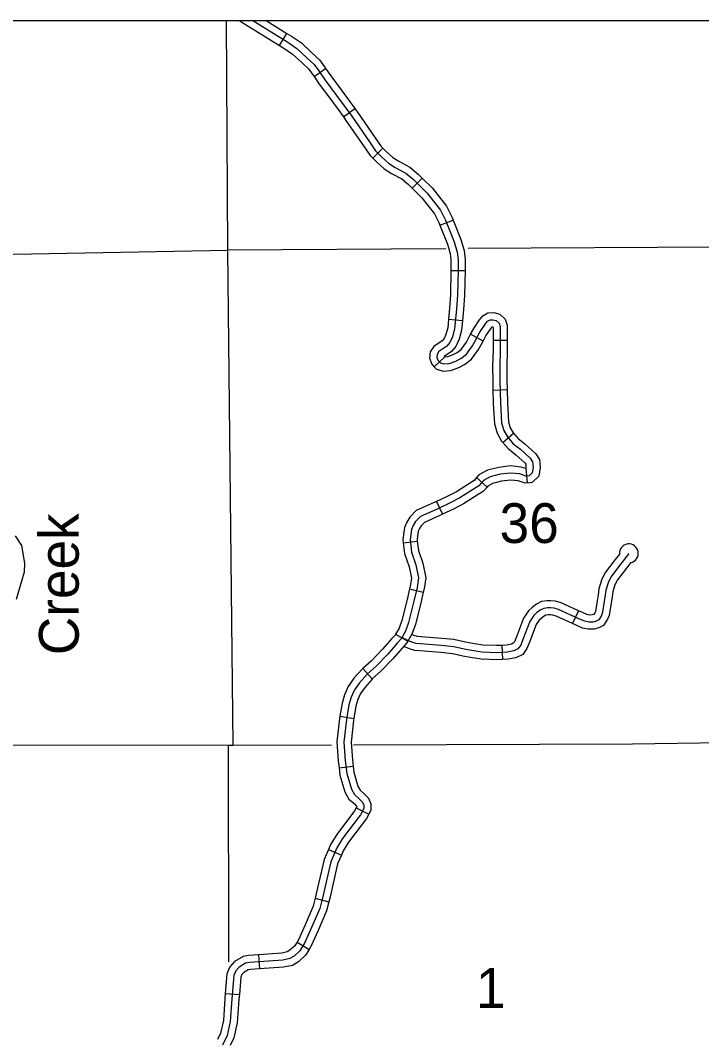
# Model space of a CAD drawing. Extents: x 1373862 to 1376999, y 1168398 to 1170455.
# Drawn here: x 1375410.3 to 1375555, y 1169362.9 to 1169579.4 of the extents above; entities that cross this region are included whole.
import ezdxf

# ---------------------------------------------------------------- set-up
doc = ezdxf.new("R2010")
doc.units = 0
for name, color, linetype in [('Level 32', 7, 'Continuous'), ('Level 35', 7, 'Continuous'), ('Level 4', 7, 'Continuous'), ('Level 45', 7, 'Continuous'), ('Level 5', 7, 'Continuous'), ('R_Draft', 7, 'Continuous')]:
    doc.layers.add(name, color=color, linetype=linetype)

msp = doc.modelspace()

# ---------------------------------------------------------------- linework, layer by layer
at = {"layer": 'Level 32'}
for p, q in [((1375465.34, 1169574.11), (1375466.93, 1169576.66)), ((1375472.67, 1169567.5), (1375475.14, 1169569.22)), ((1375478.91, 1169558.93), (1375481.32, 1169560.71)), ((1375485.15, 1169550.15), (1375487.27, 1169552.27)), ((1375493.52, 1169543.8), (1375495.63, 1169545.93)), ((1375499.42, 1169535.92), (1375502.22, 1169537.01)), ((1375501.76, 1169526.31), (1375504.76, 1169526.31)), ((1375501.22, 1169515.91), (1375504.21, 1169515.64)), ((1375508.58, 1169511.29), (1375505.94, 1169512.73)), ((1375510.69, 1169511.49), (1375513.69, 1169511.49)), ((1375498.22, 1169505.82), (1375500.4, 1169507.88)), ((1375510.67, 1169500.89), (1375513.67, 1169500.97)), ((1375512.78, 1169489.74), (1375515.05, 1169491.7)), ((1375517.63, 1169484.21), (1375517.93, 1169481.14)), ((1375507.19, 1169482.27), (1375509.44, 1169480.28)), ((1375498.69, 1169477.22), (1375499.96, 1169474.5)), ((1375491.62, 1169468.43), (1375494.61, 1169468.76)), ((1375492.96, 1169458.65), (1375495.88, 1169457.96)), ((1375490.01, 1169449), (1375492.62, 1169447.53)), ((1375483.06, 1169441.75), (1375485.04, 1169439.5)), ((1375478.17, 1169431.56), (1375481.14, 1169431.09)), ((1375477.98, 1169420.65), (1375480.96, 1169420.99)), ((1375481.65, 1169412.14), (1375484.3, 1169410.74)), ((1375475.75, 1169403.29), (1375478.5, 1169402.09)), ((1375472.91, 1169392.89), (1375475.83, 1169392.17)), ((1375469.06, 1169383.6), (1375471.61, 1169382.01)), ((1375460.89, 1169380.91), (1375461.11, 1169377.91)), ((1375453.82, 1169372.68), (1375456.81, 1169372.42))]:
    msp.add_line(p, q, dxfattribs=at)
for points in [[(1375456.69, 1169579.43), (1375457.37, 1169579.07), (1375465.34, 1169574.11)], [(1375459.64, 1169579.43), (1375467.08, 1169574.8), (1375469.05, 1169573.45), (1375471.09, 1169571.54), (1375472.67, 1169570.03), (1375473.66, 1169568.71), (1375475.01, 1169566.76), (1375477.42, 1169563.5), (1375480.68, 1169559.06), (1375484.43, 1169553.62), (1375485.75, 1169551.68), (1375486.9, 1169550.52), (1375488.51, 1169549.11), (1375489.9, 1169548.18), (1375492.17, 1169547), (1375493.78, 1169545.65), (1375496.71, 1169542.75), (1375499.54, 1169539.12), (1375500.63, 1169536.95), (1375502.41, 1169532.4), (1375503.07, 1169530.2), (1375503.26, 1169528.55), (1375503.26, 1169526.28), (1375503.17, 1169521.03), (1375502.94, 1169518.14), (1375502.54, 1169513.85), (1375502.11, 1169512.17), (1375501.55, 1169510.99), (1375500.89, 1169510.23), (1375499.21, 1169509.08), (1375498.79, 1169508.45), (1375498.72, 1169507.86), (1375498.98, 1169507.2), (1375499.51, 1169506.64), (1375500.24, 1169506.44), (1375501.39, 1169506.51), (1375502.8, 1169507.03), (1375503.86, 1169507.56), (1375505.04, 1169508.48), (1375506.33, 1169510.3), (1375507.91, 1169513.19), (1375509.06, 1169514.94), (1375509.52, 1169515.5), (1375510.05, 1169515.8), (1375510.67, 1169515.83), (1375511.36, 1169515.63), (1375511.96, 1169515.1), (1375512.19, 1169514.42), (1375512.19, 1169509.25), (1375512.1, 1169505.95), (1375512.12, 1169502.83), (1375512.25, 1169498.07), (1375512.52, 1169493.92)], [(1375462.48, 1169579.43), (1375466.93, 1169576.66)], [(1375466.93, 1169576.66), (1375467.9, 1169576.06), (1375469.99, 1169574.63), (1375472.13, 1169572.63), (1375473.8, 1169571.02), (1375474.88, 1169569.59), (1375475.14, 1169569.22)], [(1375465.34, 1169574.11), (1375466.26, 1169573.55), (1375468.11, 1169572.28), (1375470.06, 1169570.45), (1375471.55, 1169569.03), (1375472.45, 1169567.83), (1375472.67, 1169567.5)], [(1375475.14, 1169569.22), (1375476.23, 1169567.64), (1375478.62, 1169564.39), (1375481.32, 1169560.71)], [(1375472.67, 1169567.5), (1375473.79, 1169565.89), (1375476.21, 1169562.61), (1375478.91, 1169558.93)], [(1375481.32, 1169560.71), (1375481.9, 1169559.93), (1375485.67, 1169554.47), (1375486.91, 1169552.64), (1375487.27, 1169552.27)], [(1375478.91, 1169558.93), (1375479.45, 1169558.19), (1375483.19, 1169552.77), (1375484.58, 1169550.72), (1375485.15, 1169550.15)], [(1375487.27, 1169552.27), (1375487.93, 1169551.62), (1375489.43, 1169550.3), (1375490.66, 1169549.48), (1375493.01, 1169548.25), (1375494.79, 1169546.76), (1375495.63, 1169545.93)], [(1375485.15, 1169550.15), (1375485.87, 1169549.43), (1375487.6, 1169547.91), (1375489.13, 1169546.89), (1375491.33, 1169545.74), (1375492.77, 1169544.54), (1375493.52, 1169543.8)], [(1375495.63, 1169545.93), (1375497.83, 1169543.75), (1375500.82, 1169539.93), (1375502, 1169537.56), (1375502.22, 1169537.01)], [(1375493.52, 1169543.8), (1375495.59, 1169541.75), (1375498.27, 1169538.32), (1375499.26, 1169536.34), (1375499.42, 1169535.92)], [(1375499.42, 1169535.92), (1375500.99, 1169531.91), (1375501.59, 1169529.89), (1375501.76, 1169528.46), (1375501.76, 1169526.31)], [(1375502.22, 1169537.01), (1375503.83, 1169532.89), (1375504.54, 1169530.5), (1375504.76, 1169528.64), (1375504.76, 1169526.31)], [(1375501.76, 1169526.31), (1375501.76, 1169526.29), (1375501.67, 1169521.11), (1375501.44, 1169518.26), (1375501.22, 1169515.91)], [(1375504.76, 1169526.31), (1375504.76, 1169526.26), (1375504.66, 1169520.96), (1375504.43, 1169518.01), (1375504.21, 1169515.64)], [(1375505.94, 1169512.73), (1375506.62, 1169513.97), (1375507.85, 1169515.83), (1375508.54, 1169516.67), (1375509.62, 1169517.28), (1375510.84, 1169517.34), (1375512.11, 1169516.98), (1375513.25, 1169515.96), (1375513.69, 1169514.67), (1375513.69, 1169511.49)], [(1375501.22, 1169515.91), (1375501.06, 1169514.11), (1375500.69, 1169512.68), (1375500.28, 1169511.81), (1375499.89, 1169511.36), (1375498.13, 1169510.15), (1375497.34, 1169508.99), (1375497.19, 1169507.65), (1375497.7, 1169506.38), (1375498.22, 1169505.82)], [(1375504.21, 1169515.64), (1375504.02, 1169513.6), (1375503.53, 1169511.66), (1375502.82, 1169510.16), (1375501.9, 1169509.1), (1375500.29, 1169508), (1375500.29, 1169508), (1375500.4, 1169507.88)], [(1375508.58, 1169511.29), (1375509.19, 1169512.42), (1375510.27, 1169514.05), (1375510.49, 1169514.32), (1375510.5, 1169514.32), (1375510.62, 1169514.28), (1375510.66, 1169514.25), (1375510.69, 1169514.18), (1375510.69, 1169511.49)], [(1375500.31, 1169507.97), (1375500.39, 1169507.95), (1375501.08, 1169507.99), (1375502.2, 1169508.41), (1375503.05, 1169508.84), (1375503.95, 1169509.53), (1375505.05, 1169511.09), (1375505.94, 1169512.73)], [(1375498.22, 1169505.82), (1375498.71, 1169505.3), (1375500.08, 1169504.93), (1375501.7, 1169505.02), (1375503.4, 1169505.66), (1375504.66, 1169506.29), (1375506.14, 1169507.44), (1375507.6, 1169509.5), (1375508.58, 1169511.29)], [(1375510.69, 1169511.49), (1375510.69, 1169509.27), (1375510.6, 1169505.96), (1375510.62, 1169502.8), (1375510.67, 1169500.89)], [(1375513.69, 1169511.49), (1375513.69, 1169509.23), (1375513.6, 1169505.93), (1375513.62, 1169502.85), (1375513.67, 1169500.97)], [(1375510.67, 1169500.89), (1375510.75, 1169498), (1375511.03, 1169493.68), (1375511.55, 1169491.7), (1375512.51, 1169490.05), (1375512.78, 1169489.74)], [(1375513.67, 1169500.97), (1375513.75, 1169498.14), (1375514.01, 1169494.16), (1375514.35, 1169492.85), (1375514.96, 1169491.8), (1375515.05, 1169491.7)], [(1375512.52, 1169493.92), (1375512.95, 1169492.28), (1375513.74, 1169490.93), (1375514.99, 1169489.48), (1375516.5, 1169488.29), (1375518.61, 1169486.38), (1375519.1, 1169485.62), (1375519.2, 1169484.5), (1375519, 1169483.32), (1375518.35, 1169482.69), (1375517.65, 1169482.62), (1375516.37, 1169483.05), (1375514.43, 1169483.25), (1375512.19, 1169482.99), (1375510.05, 1169482.43), (1375508.66, 1169481.67), (1375507.68, 1169480.55), (1375503.67, 1169477.98), (1375501.62, 1169476.93), (1375498.79, 1169475.61), (1375495.26, 1169474.03), (1375494.21, 1169472.97), (1375493.71, 1169472.13), (1375493.35, 1169471.28), (1375493.06, 1169469.12), (1375493.35, 1169466.45), (1375494.31, 1169463.72), (1375494.87, 1169460.98), (1375494.57, 1169458.94), (1375493.89, 1169456.03), (1375492.76, 1169451.49), (1375492.1, 1169449.67), (1375491.18, 1169448.03), (1375490.36, 1169447.08), (1375488.32, 1169444.8), (1375485.85, 1169442.2), (1375483.94, 1169440.52), (1375482.32, 1169438.71), (1375481.24, 1169437.16), (1375480.54, 1169435.61), (1375480.08, 1169434.03), (1375479.59, 1169430.9), (1375479.03, 1169426.09), (1375479.31, 1169422.17), (1375479.63, 1169419.39), (1375480.61, 1169416.1), (1375481.27, 1169414.92), (1375482.22, 1169414.09), (1375482.95, 1169413.34), (1375483.25, 1169412.68), (1375483.25, 1169411.95), (1375482.55, 1169410.65), (1375478.73, 1169405.63), (1375477.53, 1169403.64), (1375476.24, 1169400.66), (1375474.62, 1169393.55), (1375473.93, 1169390.71), (1375472.15, 1169386.66), (1375470.67, 1169383.33), (1375469.68, 1169381.75), (1375468.46, 1169380.63), (1375467.54, 1169380.07), (1375466.02, 1169379.78), (1375458.94, 1169379.26)], [(1375515.05, 1169491.7), (1375516.03, 1169490.57), (1375517.47, 1169489.44), (1375519.76, 1169487.36), (1375520.56, 1169486.13), (1375520.71, 1169484.44), (1375520.4, 1169482.58), (1375519, 1169481.25), (1375518.48, 1169481.2)], [(1375512.78, 1169489.74), (1375513.95, 1169488.39), (1375515.53, 1169487.14), (1375517.46, 1169485.4), (1375517.64, 1169485.12), (1375517.69, 1169484.56), (1375517.63, 1169484.21)], [(1375517.63, 1169484.21), (1375516.69, 1169484.53), (1375514.42, 1169484.76), (1375511.91, 1169484.46), (1375509.49, 1169483.83), (1375507.71, 1169482.86), (1375507.19, 1169482.27)], [(1375507.19, 1169482.27), (1375506.69, 1169481.7), (1375502.92, 1169479.28), (1375500.96, 1169478.27), (1375498.69, 1169477.22)], [(1375518.48, 1169481.2), (1375517.48, 1169481.1), (1375516.05, 1169481.58), (1375514.44, 1169481.74), (1375512.47, 1169481.51), (1375510.61, 1169481.02), (1375509.62, 1169480.48), (1375509.44, 1169480.28)], [(1375509.44, 1169480.28), (1375508.66, 1169479.4), (1375504.42, 1169476.68), (1375502.28, 1169475.58), (1375499.96, 1169474.5)], [(1375498.69, 1169477.22), (1375498.16, 1169476.97), (1375494.4, 1169475.28), (1375493.01, 1169473.9), (1375492.37, 1169472.8), (1375491.89, 1169471.68), (1375491.55, 1169469.14), (1375491.62, 1169468.43)], [(1375499.96, 1169474.5), (1375499.41, 1169474.24), (1375496.13, 1169472.77), (1375495.41, 1169472.05), (1375495.05, 1169471.45), (1375494.81, 1169470.88), (1375494.57, 1169469.1), (1375494.61, 1169468.76)], [(1375494.61, 1169468.76), (1375494.83, 1169466.78), (1375495.76, 1169464.11), (1375496.39, 1169461.02), (1375496.05, 1169458.66), (1375495.88, 1169457.96)], [(1375491.62, 1169468.43), (1375491.88, 1169466.12), (1375492.86, 1169463.32), (1375493.35, 1169460.94), (1375493.1, 1169459.22), (1375492.96, 1169458.65)], [(1375492.96, 1169458.65), (1375492.43, 1169456.38), (1375491.33, 1169451.93), (1375490.73, 1169450.3), (1375490.01, 1169449)], [(1375495.88, 1169457.96), (1375495.34, 1169455.67), (1375494.2, 1169451.05), (1375493.47, 1169449.04), (1375492.62, 1169447.53)], [(1375490.01, 1169449), (1375489.95, 1169448.9), (1375489.23, 1169448.07), (1375487.21, 1169445.82), (1375484.8, 1169443.28), (1375483.06, 1169441.75)], [(1375492.62, 1169447.53), (1375492.41, 1169447.17), (1375491.48, 1169446.09), (1375489.42, 1169443.79), (1375486.89, 1169441.12), (1375485.04, 1169439.5)], [(1375483.06, 1169441.75), (1375482.88, 1169441.59), (1375481.14, 1169439.64), (1375479.93, 1169437.91), (1375479.13, 1169436.13), (1375478.62, 1169434.36), (1375478.17, 1169431.56)], [(1375485.04, 1169439.5), (1375485, 1169439.46), (1375483.5, 1169437.78), (1375482.55, 1169436.42), (1375481.96, 1169435.1), (1375481.55, 1169433.7), (1375481.14, 1169431.09)], [(1375478.17, 1169431.56), (1375478.1, 1169431.11), (1375477.52, 1169426.12), (1375477.82, 1169422.03), (1375477.98, 1169420.65)], [(1375481.14, 1169431.09), (1375481.08, 1169430.7), (1375480.54, 1169426.05), (1375480.81, 1169422.31), (1375480.96, 1169420.99)], [(1375477.98, 1169420.65), (1375478.16, 1169419.09), (1375479.22, 1169415.52), (1375480.09, 1169413.96), (1375481.19, 1169413.01), (1375481.69, 1169412.49), (1375481.75, 1169412.36), (1375481.75, 1169412.33), (1375481.65, 1169412.14)], [(1375480.96, 1169420.99), (1375481.11, 1169419.69), (1375482, 1169416.69), (1375482.45, 1169415.88), (1375483.26, 1169415.18), (1375484.21, 1169414.19), (1375484.75, 1169413), (1375484.75, 1169411.58), (1375484.3, 1169410.74)], [(1375481.65, 1169412.14), (1375481.28, 1169411.46), (1375477.49, 1169406.47), (1375476.2, 1169404.33), (1375475.75, 1169403.29)], [(1375484.3, 1169410.74), (1375483.82, 1169409.84), (1375479.98, 1169404.79), (1375478.87, 1169402.95), (1375478.5, 1169402.09)], [(1375475.75, 1169403.29), (1375474.8, 1169401.13), (1375473.16, 1169393.89), (1375472.91, 1169392.89)], [(1375478.5, 1169402.09), (1375477.67, 1169400.19), (1375476.08, 1169393.2), (1375475.83, 1169392.17)], [(1375472.91, 1169392.89), (1375472.5, 1169391.2), (1375470.78, 1169387.27), (1375469.34, 1169384.04), (1375469.06, 1169383.6)], [(1375475.83, 1169392.17), (1375475.35, 1169390.23), (1375473.52, 1169386.05), (1375471.99, 1169382.63), (1375471.61, 1169382.01)], [(1375469.06, 1169383.6), (1375468.51, 1169382.72), (1375467.56, 1169381.84), (1375466.99, 1169381.49), (1375465.83, 1169381.27), (1375460.89, 1169380.91)], [(1375460.89, 1169380.91), (1375458.72, 1169380.75), (1375457.61, 1169380.5), (1375455.81, 1169379.47), (1375454.79, 1169378.31), (1375454.18, 1169376.84), (1375453.82, 1169372.68)], [(1375471.61, 1169382.01), (1375470.84, 1169380.79), (1375469.37, 1169379.43), (1375468.09, 1169378.65), (1375466.22, 1169378.29), (1375461.11, 1169377.91)], [(1375458.94, 1169379.26), (1375458.15, 1169379.08), (1375456.77, 1169378.29), (1375456.08, 1169377.5), (1375455.65, 1169376.48), (1375455.22, 1169371.51), (1375454.89, 1169366.7), (1375454.2, 1169363.77), (1375453.25, 1169361.69)], [(1375461.11, 1169377.91), (1375459.16, 1169377.77), (1375458.7, 1169377.67), (1375457.73, 1169377.12), (1375457.37, 1169376.7), (1375457.13, 1169376.12), (1375456.81, 1169372.42)], [(1375453.82, 1169372.68), (1375453.73, 1169371.62), (1375453.41, 1169366.92), (1375452.78, 1169364.26), (1375452.14, 1169362.87)], [(1375456.81, 1169372.42), (1375456.72, 1169371.39), (1375456.38, 1169366.47), (1375455.63, 1169363.27), (1375454.87, 1169361.62)]]:
    msp.add_lwpolyline(points, dxfattribs=at)
at = {"layer": 'Level 35'}
msp.add_lwpolyline([(1375409.2, 1169469.93), (1375410.54, 1169467.82), (1375411.21, 1169464.11), (1375411.1, 1169462.16), (1375409.42, 1169456.37)], dxfattribs=at)
at = {"layer": 'Level 4'}
for points in [[(1375141.28, 1169422.97), (1375218.46, 1169423.68), (1375243.37, 1169424.03), (1375244.34, 1169424.04), (1375348.71, 1169425.54), (1375349.94, 1169425.54), (1375454.46, 1169425.4), (1375455.43, 1169425.4), (1375476.41, 1169425.48)], [(1375481.04, 1169425.5), (1375540.28, 1169425.73), (1375559.39, 1169426.01)]]:
    msp.add_lwpolyline(points, dxfattribs=at)
at = {"layer": 'Level 45'}
for p, q in [((1375528.82, 1169453.99), (1375527.58, 1169451.26)), ((1375512.57, 1169446.64), (1375512.73, 1169443.64))]:
    msp.add_line(p, q, dxfattribs=at)
for points in [[(1375539.54, 1169466.19), (1375537.85, 1169463.96), (1375535.86, 1169461.36), (1375535.2, 1169460.1), (1375534.65, 1169458.34), (1375534.23, 1169455.45), (1375533.88, 1169453.41), (1375533.67, 1169452.87), (1375533.13, 1169452.05), (1375532.59, 1169451.78), (1375531.95, 1169451.6), (1375531.05, 1169451.57), (1375530.17, 1169451.75), (1375528.94, 1169452.29), (1375524.62, 1169454.25), (1375523.66, 1169454.56), (1375522.93, 1169454.62), (1375522.3, 1169454.62), (1375521.45, 1169454.5), (1375520.73, 1169454.1), (1375519.95, 1169453.53), (1375519.34, 1169452.99), (1375518.53, 1169451.72), (1375517.05, 1169447.89), (1375516.57, 1169446.68), (1375515.99, 1169445.89), (1375515.09, 1169445.44), (1375513.7, 1169445.2), (1375511.47, 1169445.08), (1375508.33, 1169445.17), (1375506.16, 1169445.56), (1375504.56, 1169445.83), (1375502.39, 1169446.35), (1375499.7, 1169446.62), (1375495.3, 1169446.95), (1375494.36, 1169447.04), (1375493.46, 1169447.31), (1375492.61, 1169447.64), (1375491.33, 1169448.29)], [(1375537.55, 1169466.04), (1375536.66, 1169464.87), (1375534.59, 1169462.17), (1375533.8, 1169460.67), (1375533.19, 1169458.68), (1375532.99, 1169457.35)], [(1375539.94, 1169464.23), (1375539.05, 1169463.05), (1375537.13, 1169460.55), (1375536.59, 1169459.52), (1375536.12, 1169458.01), (1375535.96, 1169456.92)], [(1375528.82, 1169453.99), (1375525.16, 1169455.66), (1375523.95, 1169456.04), (1375523, 1169456.12), (1375522.19, 1169456.12), (1375520.98, 1169455.94), (1375519.93, 1169455.37), (1375519, 1169454.7), (1375518.19, 1169453.97), (1375517.65, 1169453.13)], [(1375535.96, 1169456.92), (1375535.71, 1169455.21), (1375535.34, 1169453.01), (1375535.01, 1169452.17), (1375534.16, 1169450.89), (1375533.13, 1169450.38), (1375532.19, 1169450.11), (1375530.92, 1169450.06), (1375529.72, 1169450.31), (1375528.32, 1169450.92), (1375527.58, 1169451.26)], [(1375532.99, 1169457.35), (1375532.75, 1169455.68), (1375532.43, 1169453.81), (1375532.33, 1169453.56), (1375532.1, 1169453.21), (1375532.04, 1169453.18), (1375531.72, 1169453.09), (1375531.18, 1169453.07), (1375530.63, 1169453.19), (1375529.55, 1169453.66), (1375528.82, 1169453.99)], [(1375517.65, 1169453.13), (1375517.18, 1169452.4), (1375515.65, 1169448.43), (1375515.24, 1169447.41), (1375515, 1169447.07), (1375514.62, 1169446.88), (1375513.53, 1169446.69), (1375512.57, 1169446.64)], [(1375520.17, 1169451.5), (1375519.87, 1169451.04), (1375518.45, 1169447.34), (1375517.89, 1169445.95), (1375516.99, 1169444.71), (1375515.56, 1169444), (1375513.87, 1169443.71), (1375512.73, 1169443.64)], [(1375527.58, 1169451.26), (1375524.09, 1169452.85), (1375523.37, 1169453.08), (1375522.87, 1169453.12), (1375522.41, 1169453.12), (1375521.93, 1169453.05), (1375521.53, 1169452.83), (1375520.89, 1169452.36), (1375520.5, 1169452.01), (1375520.17, 1169451.5)], [(1375502.36, 1169447.86), (1375499.84, 1169448.11), (1375495.43, 1169448.44), (1375494.65, 1169448.52), (1375493.95, 1169448.73), (1375493.41, 1169448.94)], [(1375512.57, 1169446.64), (1375511.45, 1169446.58), (1375508.49, 1169446.67), (1375506.42, 1169447.04), (1375504.86, 1169447.3), (1375502.64, 1169447.83), (1375502.36, 1169447.86)], [(1375502.06, 1169444.87), (1375499.57, 1169445.12), (1375495.17, 1169445.46), (1375494.07, 1169445.56), (1375492.97, 1169445.89), (1375491.74, 1169446.37)], [(1375512.73, 1169443.64), (1375511.49, 1169443.58), (1375508.18, 1169443.67), (1375505.9, 1169444.08), (1375504.26, 1169444.36), (1375502.14, 1169444.86), (1375502.06, 1169444.87)]]:
    msp.add_lwpolyline(points, dxfattribs=at)
msp.add_arc((1375539.54, 1169466.19), 2, 281.4872, 184.307, dxfattribs=at)
at = {"layer": 'Level 5'}
for points in [[(1375454.02, 1169579.43), (1375454.3, 1169530.61)], [(1375348.25, 1169528.62), (1375454.3, 1169530.61)], [(1375500.69, 1169530.9), (1375454.3, 1169530.61)], [(1375454.3, 1169530.61), (1375455.43, 1169425.4)], [(1375559, 1169531.27), (1375505.39, 1169530.93)], [(1375454.46, 1169425.4), (1375454.54, 1169379.4)]]:
    msp.add_lwpolyline(points, dxfattribs=at)
at = {"layer": 'R_Draft'}
msp.add_lwpolyline([(1374675.34, 1169579.43), (1376182.76, 1169579.43), (1376182.76, 1168562.99), (1374675.34, 1168562.99)], close=True, dxfattribs=at)

# ---------------------------------------------------------------- texts
at = {"layer": 'Level 35'}
msp.add_text('Creek', height=8.448, rotation=90, dxfattribs=at).set_placement((1375422.7, 1169444.56))
at = {"layer": 'Level 5'}
for s, height, p in [('36', 8.448, (1375512.08, 1169468.39)), ('1', 8.45, (1375507.05, 1169369.62))]:
    msp.add_text(s, height=height, dxfattribs=at).set_placement(p)

doc.saveas('drawing.dxf')
